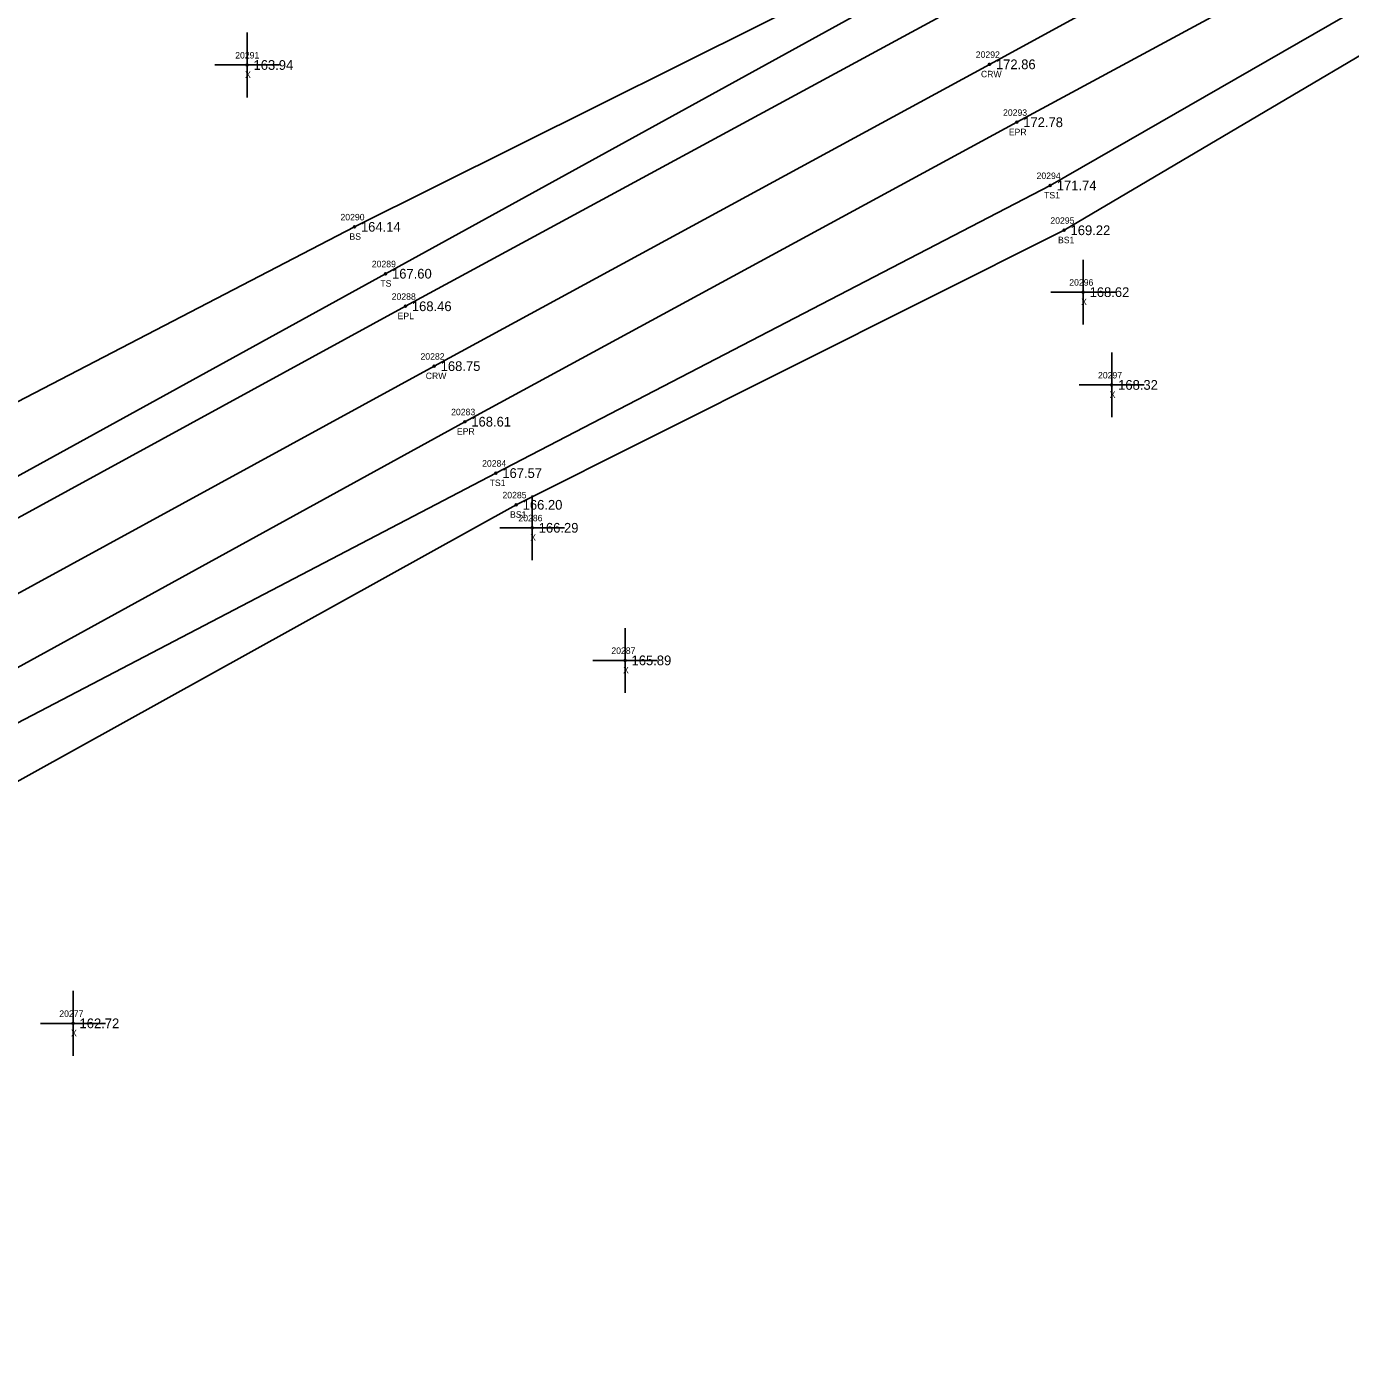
# Model space of a CAD drawing. Extents: x 2279528 to 2280976, y 1061373 to 1062235.
# Drawn here: x 2280424.4 to 2280628.7, y 1061781 to 1061988.9 of the extents above; entities that cross this region are included whole.
import ezdxf

# ---------------------------------------------------------------- set-up
doc = ezdxf.new("R2010")
doc.units = 0
for name, color, linetype in [('RD_DTM_BkLn1', 7, 'Continuous'), ('RD_DTM_BkLn2', 7, 'Continuous'), ('RD_DTM_BkLn_txCode', 7, 'Continuous'), ('RD_EX_Misc', 7, 'Continuous'), ('RD_EX_Misc_txCode', 7, 'Continuous'), ('RD_EX_Road', 7, 'Continuous'), ('RD_EX_Road_txCode', 7, 'Continuous'), ('RD_EX_TX_Misc_ELEV', 7, 'Continuous'), ('RD_EX_TX_Road_ELEV', 7, 'Continuous'), ('RD_HC_Survey_ELEV', 7, 'Continuous'), ('RD_HC_Survey_txCode', 7, 'Continuous'), ('RD_SMD_Locator', 7, 'Continuous')]:
    doc.layers.add(name, color=color, linetype=linetype)

msp = doc.modelspace()

# ---------------------------------------------------------------- linework, layer by layer
at = {"layer": 'RD_DTM_BkLn1'}
msp.add_lwpolyline([(2279559.79, 1061433.13), (2279641.23, 1061477.49), (2279727.93, 1061524.84), (2279814.76, 1061571.75), (2279901.26, 1061618.64), (2279982.8, 1061662.56), (2280064.7, 1061706.86), (2280148.08, 1061751.86), (2280234.22, 1061798.46), (2280310.96, 1061840.01), (2280397.69, 1061887.57), (2280487.27, 1061936.5), (2280573.03, 1061983.12), (2280654.64, 1062027.66), (2280741.28, 1062074.45), (2280833.39, 1062123.87), (2280892.52, 1062155.9), (2280939.46, 1062181.85)], dxfattribs=at)
at = {"layer": 'RD_DTM_BkLn2'}
for points in [[(2280244.17, 1061836.72), (2280279.92, 1061859.99), (2280384.06, 1061910.85), (2280474.95, 1061958.02), (2280563.04, 1062001.93), (2280638.18, 1062044.64), (2280638.45, 1062052), (2280636.3, 1062090.14)], [(2280254.15, 1061833.04), (2280297.35, 1061859.31), (2280389.94, 1061901.4), (2280479.75, 1061950.78), (2280565.23, 1061997.82), (2280647.02, 1062043.23), (2280646.04, 1062059.26), (2280636.3, 1062090.14)], [(2280272.88, 1061795.9), (2280297.58, 1061791.78), (2280309.49, 1061810.68), (2280320.64, 1061820.76), (2280406.65, 1061872.9), (2280496.79, 1061919.98), (2280582.43, 1061964.41), (2280663.95, 1062011.32), (2280685.25, 1062021.45), (2280750.74, 1062056.04), (2280766.13, 1062062.47), (2280799.22, 1062079.83)], [(2280270.02, 1061790.74), (2280279.94, 1061788.98), (2280298.7, 1061789.36), (2280312.74, 1061804.74), (2280323.13, 1061815.81), (2280411.42, 1061866.03), (2280499.93, 1061915.08), (2280584.56, 1061957.49), (2280666.91, 1062006.18), (2280674.46, 1062011.72), (2280685.18, 1062009.25), (2280689.93, 1062011.32), (2280693.25, 1062019.83), (2280753.26, 1062052.49), (2280766.38, 1062057.83), (2280800.29, 1062072.08)]]:
    msp.add_lwpolyline(points, dxfattribs=at)
at = {"layer": 'RD_EX_Misc'}
for p, q in [((2280458.36, 1061978.02), (2280458.36, 1061988.02)), ((2280453.36, 1061983.02), (2280463.36, 1061983.02)), ((2280587.5, 1061942.93), (2280587.5, 1061952.93)), ((2280582.5, 1061947.93), (2280592.5, 1061947.93)), ((2280591.91, 1061928.6), (2280591.91, 1061938.6)), ((2280586.91, 1061933.6), (2280596.91, 1061933.6)), ((2280502.41, 1061906.53), (2280502.41, 1061916.53)), ((2280497.41, 1061911.53), (2280507.41, 1061911.53)), ((2280516.75, 1061886.05), (2280516.75, 1061896.05)), ((2280511.75, 1061891.05), (2280521.75, 1061891.05)), ((2280431.48, 1061829.98), (2280431.48, 1061839.98)), ((2280426.48, 1061834.98), (2280436.48, 1061834.98))]:
    msp.add_line(p, q, dxfattribs=at)
at = {"layer": 'RD_EX_Road'}
for points in [[(2279554.31, 1061441.46), (2279636.61, 1061486.51), (2279673.46, 1061506.76), (2279683.06, 1061512.21), (2279723.14, 1061533.54), (2279809.28, 1061580.29), (2279896.91, 1061627.91), (2279977.07, 1061671.02), (2280059.64, 1061715.57), (2280142.91, 1061760.72), (2280228.83, 1061807.06), (2280306.04, 1061849.18), (2280392.98, 1061896.71), (2280482.82, 1061945.75), (2280567.83, 1061991.78), (2280649.94, 1062036.55), (2280660.56, 1062042.19), (2280676.12, 1062050.66), (2280737.28, 1062083.64), (2280828.54, 1062132.77), (2280887.86, 1062164.61), (2280934.91, 1062190.9)], [(2280403.05, 1061879.04), (2280492, 1061927.92), (2280577.25, 1061974.17), (2280660.08, 1062018.91), (2280745.99, 1062065.19), (2280838.21, 1062115.39), (2280896.66, 1062146.92), (2280943.94, 1062172.8)]]:
    msp.add_lwpolyline(points, dxfattribs=at)
at = {"layer": 'RD_SMD_Locator'}
for centre in [(2280458.36, 1061983.02), (2280573.03, 1061983.12), (2280577.25, 1061974.17), (2280582.43, 1061964.41), (2280474.95, 1061958.02), (2280584.56, 1061957.49), (2280479.75, 1061950.78), (2280587.5, 1061947.93), (2280482.82, 1061945.75), (2280487.27, 1061936.5), (2280591.91, 1061933.6), (2280492, 1061927.92), (2280496.79, 1061919.98), (2280499.93, 1061915.08), (2280502.41, 1061911.53), (2280516.75, 1061891.05), (2280431.48, 1061834.98)]:
    msp.add_circle(centre, 0.15, dxfattribs=at)

# ---------------------------------------------------------------- texts
at = {"layer": 'RD_DTM_BkLn_txCode'}
for s, p in [('20294', (2280580.31, 1061965.41)), ('TS1', (2280581.47, 1061962.41)), ('20290', (2280472.79, 1061959.02)), ('20295', (2280582.44, 1061958.49)), ('BS', (2280474.17, 1061956.02)), ('BS1', (2280583.62, 1061955.49)), ('20289', (2280477.63, 1061951.78)), ('TS', (2280478.95, 1061948.78)), ('20284', (2280494.67, 1061920.98)), ('TS1', (2280495.83, 1061917.98)), ('20285', (2280497.81, 1061916.08)), ('BS1', (2280498.98, 1061913.08))]:
    msp.add_text(s, height=1, dxfattribs=at).set_placement(p)
at = {"layer": 'RD_EX_Misc_txCode'}
for s, p in [('20291', (2280456.53, 1061984.02)), ('X', (2280458.05, 1061981.02)), ('20296', (2280585.36, 1061948.93)), ('X', (2280587.19, 1061945.93)), ('20297', (2280589.8, 1061934.6)), ('X', (2280591.6, 1061931.6)), ('20286', (2280500.27, 1061912.53)), ('X', (2280502.1, 1061909.53)), ('20287', (2280514.63, 1061892.05)), ('X', (2280516.44, 1061889.05)), ('20277', (2280429.36, 1061835.98)), ('X', (2280431.17, 1061832.98))]:
    msp.add_text(s, height=1, dxfattribs=at).set_placement(p)
at = {"layer": 'RD_EX_Road_txCode'}
for s, p in [('20293', (2280575.13, 1061975.17)), ('EPR', (2280576.02, 1061972.17)), ('20288', (2280480.7, 1061946.75)), ('EPL', (2280481.61, 1061943.75)), ('20283', (2280489.88, 1061928.92)), ('EPR', (2280490.77, 1061925.92))]:
    msp.add_text(s, height=1, dxfattribs=at).set_placement(p)
at = {"layer": 'RD_EX_TX_Misc_ELEV'}
for s, p in [('163.94', (2280459.36, 1061982.27)), ('171.74', (2280583.43, 1061963.66)), ('164.14', (2280475.95, 1061957.27)), ('169.22', (2280585.56, 1061956.74)), ('167.60', (2280480.75, 1061950.03)), ('168.62', (2280588.5, 1061947.18)), ('168.32', (2280592.91, 1061932.85)), ('167.57', (2280497.79, 1061919.23)), ('166.20', (2280500.93, 1061914.33)), ('166.29', (2280503.41, 1061910.78)), ('165.89', (2280517.75, 1061890.3)), ('162.72', (2280432.48, 1061834.23))]:
    msp.add_text(s, height=1.5, dxfattribs=at).set_placement(p)
at = {"layer": 'RD_EX_TX_Road_ELEV'}
for s, p in [('172.78', (2280578.25, 1061973.42)), ('168.46', (2280483.82, 1061945)), ('168.61', (2280493, 1061927.17))]:
    msp.add_text(s, height=1.5, dxfattribs=at).set_placement(p)
at = {"layer": 'RD_HC_Survey_ELEV'}
for s, p in [('172.86', (2280574.03, 1061982.37)), ('168.75', (2280488.27, 1061935.75))]:
    msp.add_text(s, height=1.5, dxfattribs=at).set_placement(p)
at = {"layer": 'RD_HC_Survey_txCode'}
for s, p in [('20292', (2280570.92, 1061984.12)), ('CRW', (2280571.72, 1061981.12)), ('20282', (2280485.15, 1061937.5)), ('CRW', (2280485.96, 1061934.5))]:
    msp.add_text(s, height=1, dxfattribs=at).set_placement(p)

doc.saveas('drawing.dxf')
